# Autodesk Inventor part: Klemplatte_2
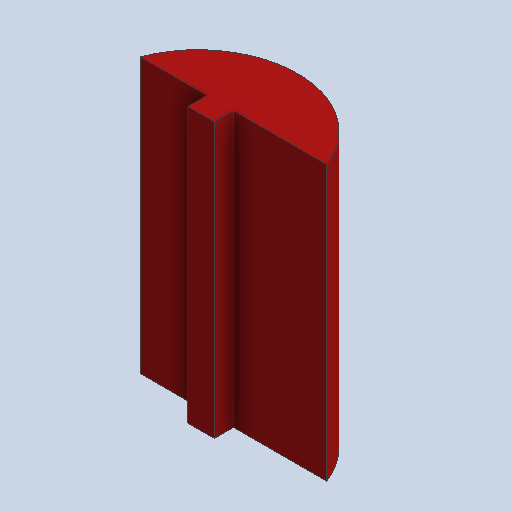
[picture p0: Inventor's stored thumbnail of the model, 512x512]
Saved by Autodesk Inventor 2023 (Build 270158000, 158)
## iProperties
Created: 2025-02
Part Number: Klemplatte_2
Material: Generisch
Document SubType Name: Modeling
Designer: MVM1
Density: 1 g/cm^3
Appearance: Vorgabe
Author: MVM1
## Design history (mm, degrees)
derived "Bauteil_Ohne_Scharnier.ipt"
feature "Klemplatte_2::Bauteil_Ohne_Scharnier.ipt" dims "d0" = 10
tag "Bezeichnung1"
node "Klemplatte_2"
